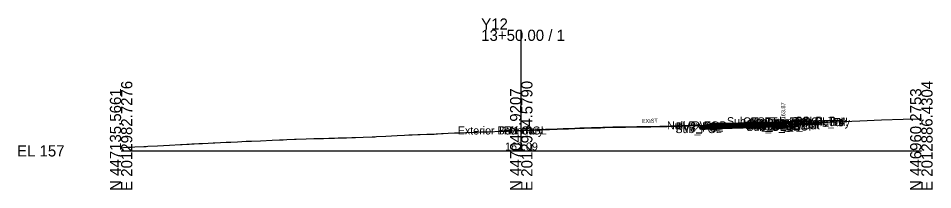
# Model space of a CAD drawing. Extents: x -26 to 1203, y -10 to 9542.
# Drawn here: x -25.7 to 202.8, y 6990.3 to 7033.1 of the extents above; entities that cross this region are included whole.
import ezdxf

# ---------------------------------------------------------------- set-up
doc = ezdxf.new("R2010")
doc.units = 0
for name, color, linetype in [('Default', 7, 'Continuous'), ('Exist Cross Section Cell', 7, 'Continuous'), ('Exist XS Center Line Elevation Label', 7, 'Continuous'), ('Exist XS Ground Line', 7, 'Continuous'), ('Prop CMT Conc Surface', 7, 'Continuous'), ('Prop CMT Concrete Structures', 7, 'Continuous'), ('Prop CMT Pvmt Course 1', 7, 'Continuous'), ('Prop CMT Pvmt Course 1 CG', 7, 'Continuous'), ('Prop CMT Pvmt Course 2', 7, 'Continuous'), ('Prop CMT Pvmt Course 3', 7, 'Continuous'), ('Prop CMT Pvmt Surface', 7, 'Continuous'), ('Prop CMT Slope Grass', 7, 'Continuous'), ('Prop CMT Subgrade Earthwork', 7, 'Continuous'), ('Prop XS Earthwork Shape', 7, 'Continuous'), ('Prop XS Finish Grade CurbGutter', 7, 'Continuous'), ('Prop XS Hydro Elevations', 7, 'Continuous'), ('Prop XS SE Text', 7, 'Continuous'), ('Scratch_Level_0', 7, 'Continuous')]:
    doc.layers.add(name, color=color, linetype=linetype)

msp = doc.modelspace()

# ---------------------------------------------------------------- linework, layer by layer
at = {"layer": 'Exist Cross Section Cell'}
for p, q in [((100, 7000), (100, 7030.26)), ((0, 7000), (100, 7000)), ((100, 7000), (200, 7000))]:
    msp.add_line(p, q, dxfattribs=at)
at = {"layer": 'Exist XS Ground Line'}
msp.add_lwpolyline([(0, 7000.8), (0.56, 7000.84), (1.51, 7000.89), (2.74, 7000.95), (3.41, 7000.99), (5.71, 7001.1), (6.26, 7001.13), (6.71, 7001.15), (9.12, 7001.27), (12.07, 7001.42), (14.84, 7001.58), (15.24, 7001.6), (16.42, 7001.67), (17.01, 7001.7), (17.72, 7001.74), (18.3, 7001.77), (19.39, 7001.83), (20.33, 7001.87), (21.72, 7001.93), (23.03, 7001.99), (23.4, 7002.01), (24.82, 7002.1), (26.27, 7002.15), (26.69, 7002.17), (27.44, 7002.21), (29.12, 7002.29), (31.22, 7002.39), (31.97, 7002.42), (32.56, 7002.45), (34.82, 7002.54), (37.74, 7002.68), (39.55, 7002.75), (40.52, 7002.79), (41.4, 7002.82), (43.37, 7002.89), (43.79, 7002.91), (46.22, 7002.98), (48.16, 7003.05), (49.07, 7003.07), (50.6, 7003.11), (51.92, 7003.15), (53.37, 7003.19), (54.28, 7003.22), (54.78, 7003.23), (55.3, 7003.25), (56.32, 7003.23), (57.63, 7003.34), (58.61, 7003.38), (60.47, 7003.44), (62.72, 7003.51), (63.5, 7003.54), (63.81, 7003.56), (66.17, 7003.69), (69.03, 7003.84), (70.81, 7003.93), (71.88, 7003.98), (72.71, 7004.01), (74.15, 7004.07), (74.75, 7004.09), (76.38, 7004.16), (77.6, 7004.2), (78.21, 7004.2), (78.71, 7004.22), (79.1, 7004.27), (80.08, 7004.32), (80.47, 7004.34), (81.77, 7004.4), (83.31, 7004.47), (84.57, 7004.52), (86.16, 7004.58), (88.15, 7004.66), (89.01, 7004.69), (89.73, 7004.72), (91.83, 7004.79), (94.92, 7004.89), (96.61, 7004.96), (97.53, 7005), (100.38, 7005.1), (100.7, 7005.11), (103.23, 7005.2), (103.96, 7005.23), (105.31, 7005.27), (106.09, 7005.3), (107.05, 7005.34), (109, 7005.4), (110.52, 7005.47), (111.37, 7005.51), (111.84, 7005.53), (113.42, 7005.58), (114.68, 7005.63), (115.73, 7005.66), (117.54, 7005.72), (119.78, 7005.79), (120.4, 7005.81), (120.9, 7005.83), (123.14, 7005.9), (123.49, 7005.91), (126.08, 7005.94), (128.92, 7005.98), (131.25, 7006.01), (131.76, 7006.01), (132.37, 7006.03), (134.63, 7006.07), (136.48, 7006.11), (137.46, 7006.13), (138.95, 7006.19), (140.32, 7006.23), (141.66, 7006.27), (143.14, 7006.31), (144.31, 7006.36), (144.72, 7006.36), (146.49, 7006.25), (147.19, 7006.79), (149.03, 7006.83), (150.5, 7006.83), (167.1, 7007.16), (167.67, 7006.67), (168.52, 7006.72), (170.75, 7006.83), (172.33, 7006.96), (173.6, 7007.05), (174.61, 7007.11), (184.61, 7007.47), (190.06, 7007.71), (195.46, 7007.88), (199.34, 7007.98), (200, 7008.01)], dxfattribs=at)
at = {"layer": 'Prop CMT Conc Surface'}
msp.add_lwpolyline([(163.49, 7006.89), (165.49, 7006.87), (165.49, 7007.37), (165.99, 7007.37)], dxfattribs=at)
at = {"layer": 'Prop CMT Concrete Structures'}
for points in [[(163.49, 7006.89), (165.49, 7006.87), (165.49, 7007.37), (165.99, 7007.37)], [(165.99, 7007.37), (165.99, 7006.38), (163.49, 7006.31)], [(163.49, 7006.31), (163.49, 7006.89)]]:
    msp.add_lwpolyline(points, dxfattribs=at)
at = {"layer": 'Prop CMT Pvmt Course 1'}
for points in [[(144.72, 7006.36), (163.49, 7006.89)], [(163.49, 7006.89), (163.49, 7006.64)], [(144.72, 7006.36), (144.72, 7006.36), (144.31, 7006.36), (143.14, 7006.31), (141.66, 7006.27), (140.32, 7006.23), (138.95, 7006.19), (137.46, 7006.13), (136.48, 7006.11), (134.63, 7006.07), (132.37, 7006.03), (131.76, 7006.01), (131.58, 7006.01), (131.25, 7006.01), (128.92, 7005.98), (126.08, 7005.94), (126.06, 7005.94), (126.04, 7005.94), (123.49, 7005.91), (123.14, 7005.9), (122.87, 7005.9), (120.9, 7005.83), (120.4, 7005.81), (119.78, 7005.79), (117.54, 7005.72), (115.73, 7005.66), (114.68, 7005.63), (113.42, 7005.58), (111.84, 7005.53), (111.37, 7005.51), (110.52, 7005.47), (109, 7005.4), (107.05, 7005.34), (106.09, 7005.3), (105.82, 7005.29), (105.31, 7005.27), (103.96, 7005.23), (103.23, 7005.2), (100.7, 7005.11), (100.38, 7005.1), (100.29, 7005.1), (100.13, 7005.09), (100, 7005.09)], [(100, 7005.09), (100, 7005.09)], [(163.49, 7006.64), (144.72, 7006.11)], [(144.72, 7006.36), (144.72, 7006.36)], [(144.72, 7006.11), (144.72, 7006.36)]]:
    msp.add_lwpolyline(points, dxfattribs=at)
at = {"layer": 'Prop CMT Pvmt Course 1 CG'}
for points in [[(163.49, 7006.31), (166.49, 7006.39), (166.82, 7006.07)], [(163.49, 7005.97), (163.49, 7006.31)], [(166.82, 7006.07), (163.49, 7005.97)]]:
    msp.add_lwpolyline(points, dxfattribs=at)
at = {"layer": 'Prop CMT Pvmt Course 2'}
for points in [[(144.72, 7006.11), (163.49, 7006.64)], [(163.49, 7006.31), (144.72, 7005.77)], [(144.72, 7005.77), (144.72, 7006.11)], [(163.49, 7006.64), (163.49, 7006.31)]]:
    msp.add_lwpolyline(points, dxfattribs=at)
at = {"layer": 'Prop CMT Pvmt Course 3'}
for points in [[(144.72, 7005.77), (163.49, 7006.31)], [(163.49, 7005.97), (144.72, 7005.44)], [(144.72, 7005.44), (144.72, 7005.77)], [(163.49, 7006.31), (163.49, 7005.97)]]:
    msp.add_lwpolyline(points, dxfattribs=at)
at = {"layer": 'Prop CMT Pvmt Surface'}
msp.add_lwpolyline([(144.72, 7006.36), (163.49, 7006.89)], dxfattribs=at)
at = {"layer": 'Prop CMT Slope Grass'}
msp.add_line((165.99, 7007.37), (179.53, 7007.64), dxfattribs=at)
msp.add_lwpolyline([(179.53, 7007.64), (179.53, 7006.31), (180.19, 7006.31), (180.19, 7007.31)], dxfattribs=at)
at = {"layer": 'Prop CMT Subgrade Earthwork'}
for points in [[(163.49, 7005.97), (166.82, 7006.07), (168.16, 7007.41)], [(144.72, 7005.44), (144.72, 7006.36)], [(144.72, 7005.44), (163.49, 7005.97)], [(163.49, 7005.97), (144.72, 7005.44)]]:
    msp.add_lwpolyline(points, dxfattribs=at)
at = {"layer": 'Prop XS Earthwork Shape'}
for points in [[(165.99, 7006.38), (163.49, 7006.31), (163.49, 7006.89), (146.7, 7006.41), (146.49, 7006.25), (144.72, 7006.36), (144.72, 7005.44), (163.49, 7005.97), (166.82, 7006.07), (167.54, 7006.79), (167.1, 7007.16), (165.99, 7007.14)], [(165.49, 7006.87), (165.49, 7007.13), (150.5, 7006.83), (149.03, 7006.83), (147.19, 7006.79), (146.7, 7006.41), (163.49, 7006.89)], [(165.99, 7006.38), (163.49, 7006.31), (163.49, 7006.89), (165.49, 7006.87), (165.49, 7007.13), (165.99, 7007.14)], [(168.16, 7007.41), (179.53, 7007.64), (179.53, 7007.29), (174.61, 7007.11), (173.6, 7007.05), (172.33, 7006.96), (170.75, 7006.83), (168.52, 7006.72), (167.67, 7006.67), (167.54, 7006.79)], [(179.53, 7006.31), (180.19, 7006.31), (180.19, 7007.31), (179.53, 7007.29)]]:
    msp.add_lwpolyline(points, close=True, dxfattribs=at)
at = {"layer": 'Prop XS Finish Grade CurbGutter'}
for p, q in [((179.53, 7007.81), (179.72, 7007.81)), ((179.53, 7007.81), (180.19, 7007.81)), ((179.53, 7007.81), (179.53, 7006.81)), ((179.53, 7006.82), (179.53, 7006.31)), ((179.53, 7006.81), (180.19, 7006.81)), ((180.19, 7007.39), (179.84, 7007.76)), ((180.19, 7007.39), (180.19, 7006.81)), ((180.19, 7007.31), (180.19, 7007.31)), ((180.19, 7006.82), (180.19, 7006.31)), ((179.53, 7006.31), (180.19, 7006.31))]:
    msp.add_line(p, q, dxfattribs=at)
msp.add_arc((179.72, 7007.64), 0.166, 43.9997, 90, dxfattribs=at)

# ---------------------------------------------------------------- texts
at = {"layer": 'Default'}
msp.add_text('-', height=0.0001, dxfattribs=at).set_placement((0, 7000))
at = {"layer": 'Exist Cross Section Cell'}
for s, p in [('Y12', (90, 7030.26)), ('13+50.00 / 1', (90, 7027.46)), ('EL 157', (-26, 6998.6))]:
    msp.add_text(s, height=2.8, dxfattribs=at).set_placement(p)
for s, p in [('E 2012982.7276', (2.8, 6990)), ('E 2012934.5790', (102.8, 6990)), ('E 2012886.4304', (202.8, 6990)), ('N 447135.5661', (0, 6990)), ('N 447047.9207', (100, 6990)), ('N 446960.2753', (200, 6990))]:
    msp.add_text(s, height=2.8, rotation=90, dxfattribs=at).set_placement(p)
at = {"layer": 'Exist XS Center Line Elevation Label'}
msp.add_text('162.09', height=2, dxfattribs=at).set_placement((95.97, 7000.09))
at = {"layer": 'Prop XS Hydro Elevations'}
msp.add_text('163.87', height=1, rotation=90, dxfattribs=at).set_placement((165.99, 7007.87))
at = {"layer": 'Prop XS SE Text'}
msp.add_text('EXIST', height=1, rotation=1.6261, dxfattribs=at).set_placement((130.15, 7006.94))
at = {"layer": 'Scratch_Level_0'}
for s, p in [('Null Ex EOP', (136.43, 7005.36)), ('PV2_PGL', (138.63, 7005.11)), ('PV1', (142.8, 7005.36)), ('Sub_Trench_Out_DLT', (151.42, 7006.41)), ('CG_Top_Face', (155.45, 7006.37)), ('CG1_Shelf_Out', (155.74, 7005.39)), ('CG_Bot_IE', (156.1, 7005.31)), ('Sub_OEOT', (156.26, 7004.97)), ('CG_Top_Gut', (156.42, 7005.87)), ('PV2_OEOT', (156.36, 7005.64)), ('PV3_OEOT', (156.36, 7005.31)), ('CG_Top_BOC', (156.97, 7006.37)), ('PV1_OEOT', (156.93, 7005.89)), ('CG_Bot_BOC', (157, 7005.38)), ('Sub_OEOP', (159.62, 7005.07)), ('Exterior Boundary', (160.76, 7006.18)), ('CSLP_Pnt', (168.36, 7006.56)), ('Slope_Fill', (169.83, 7006.18)), ('Exterior Boundary', (84.14, 7004.09)), ('PV1_PGL', (94.47, 7004.09)), ('EX CL', (95.67, 7004.09)), ('Sub_PGL', (138.54, 7004.44)), ('PV3_PGL', (138.63, 7004.77))]:
    msp.add_text(s, height=2, dxfattribs=at).set_placement(p)

doc.saveas('drawing.dxf')
